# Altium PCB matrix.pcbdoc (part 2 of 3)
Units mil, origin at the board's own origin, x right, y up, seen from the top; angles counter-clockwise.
Board outline 9450 x 9250 mil, 2 copper layers (Top Layer, Bottom Layer); 316 components, 228 nets, 906 pads, 1393 vias.
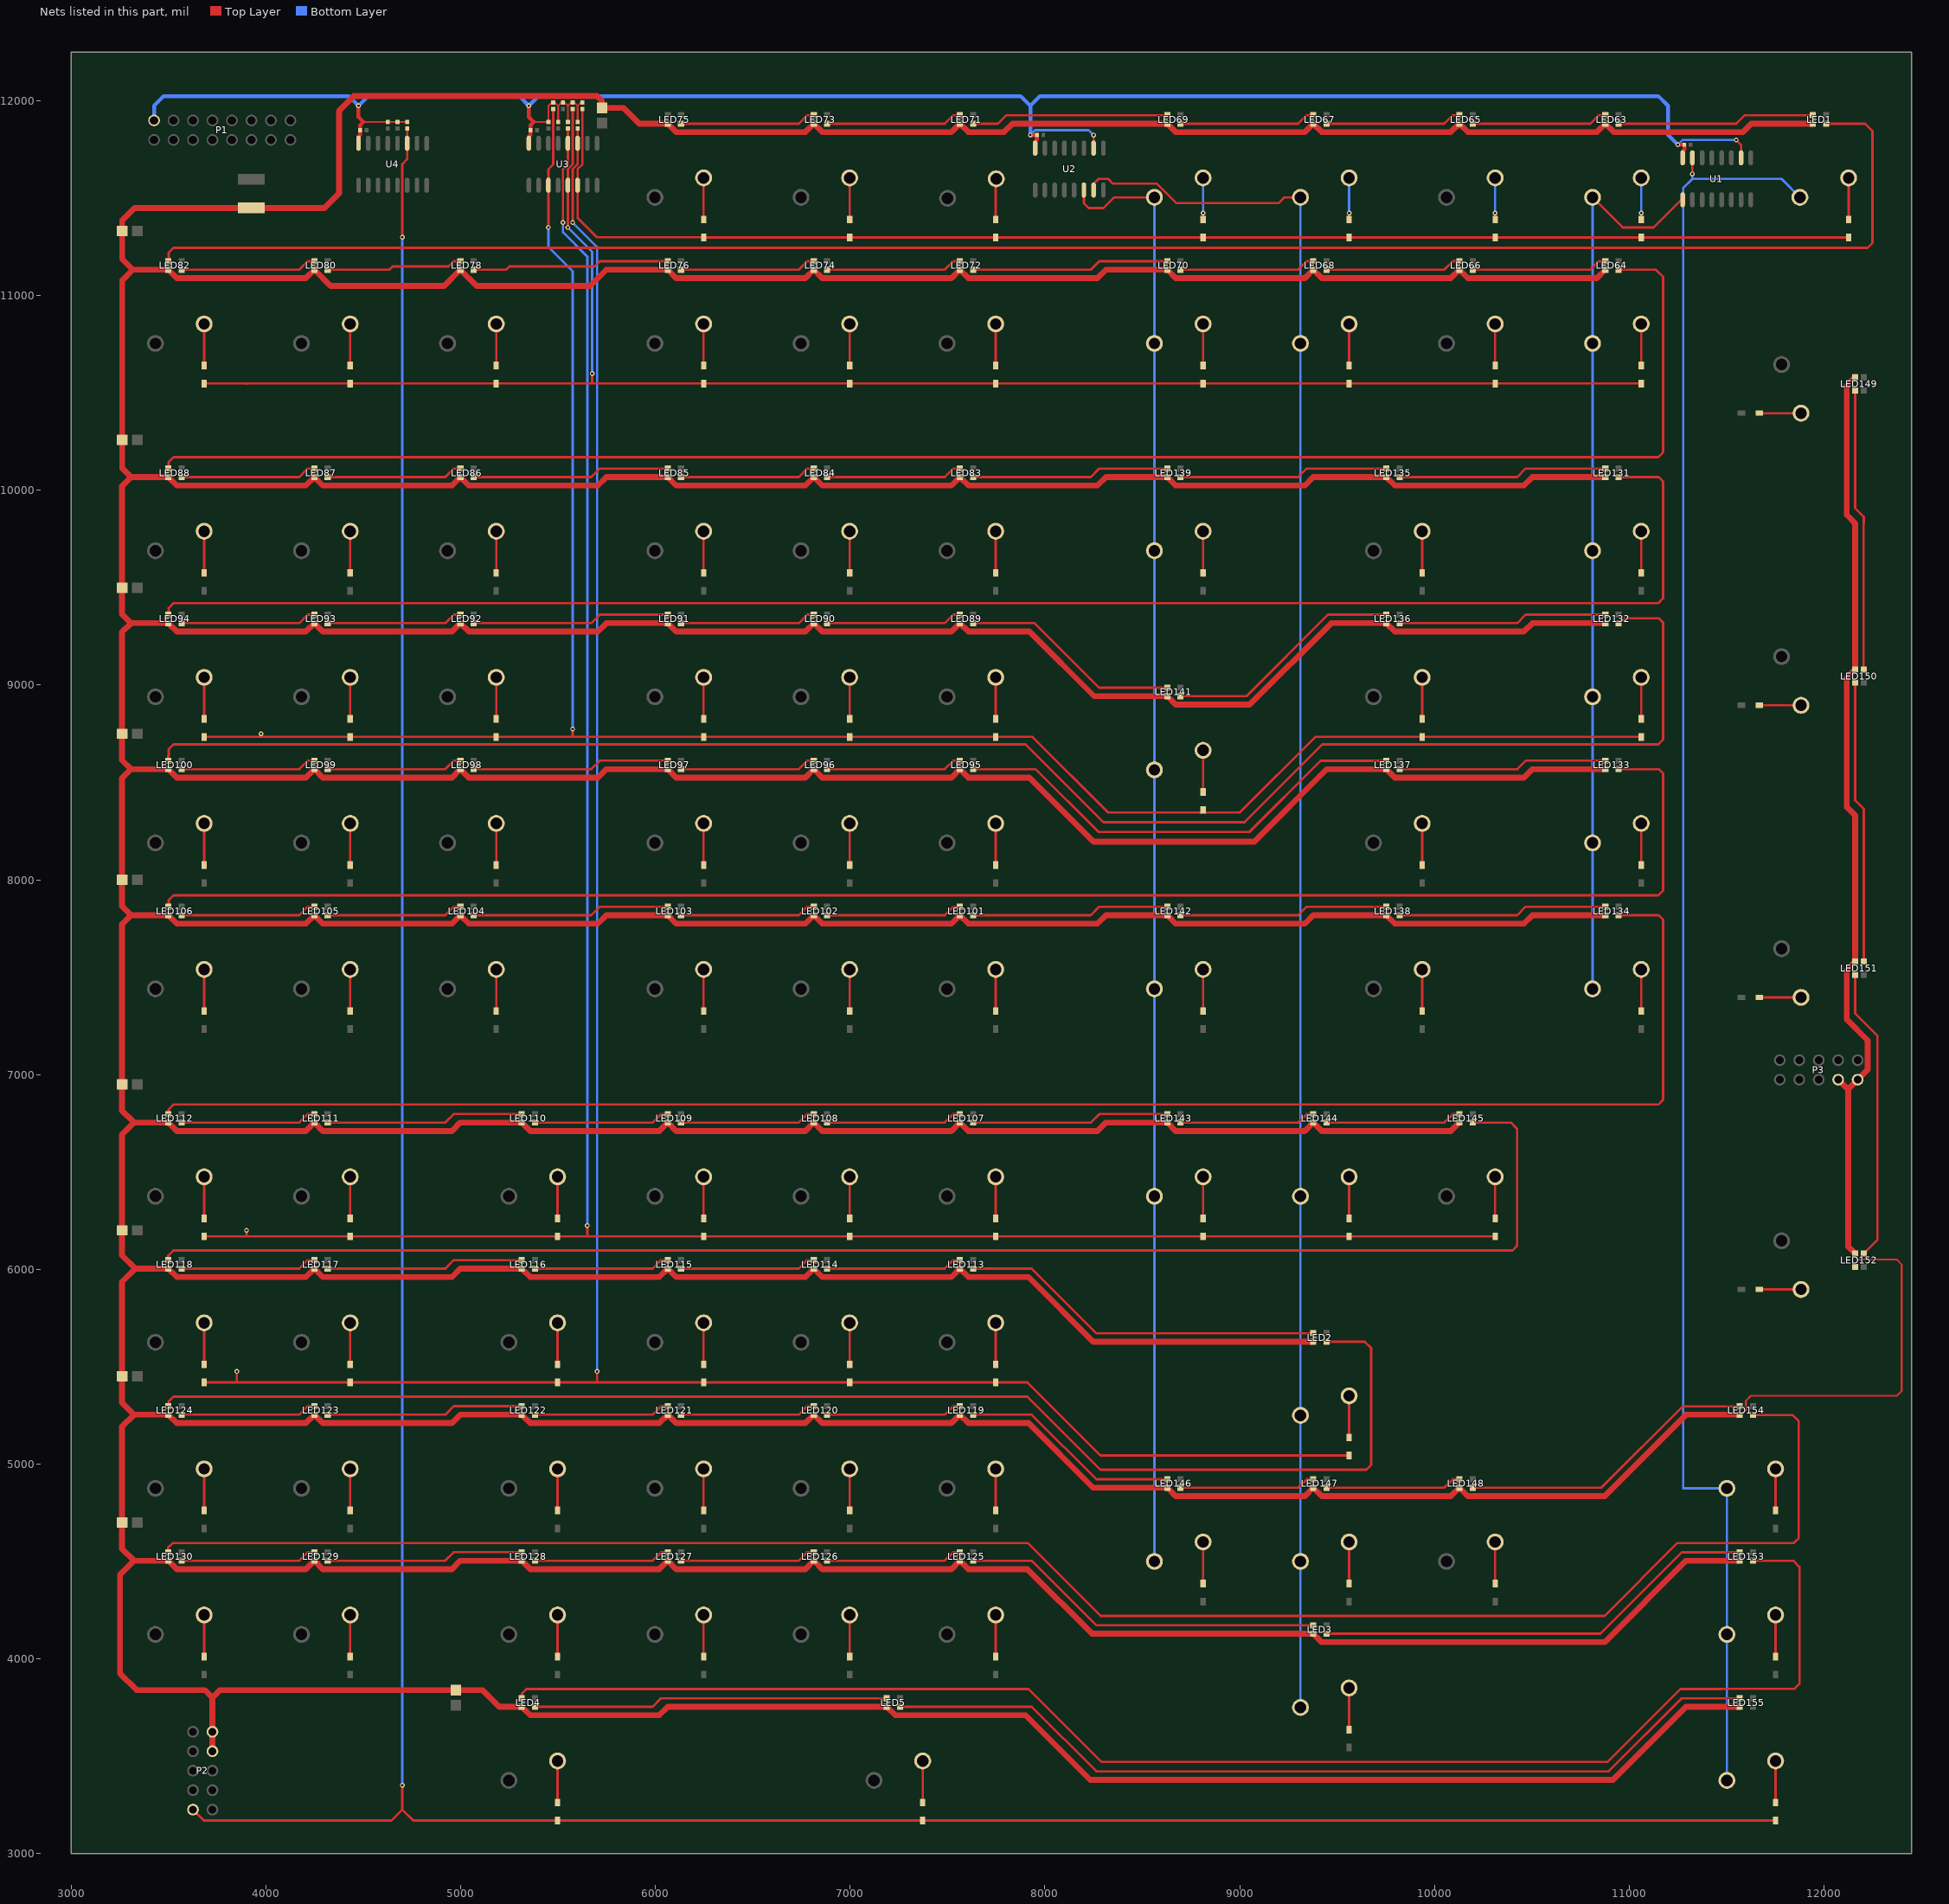
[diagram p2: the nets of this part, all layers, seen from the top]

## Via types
v1: diameter 24.02, hole 12.01, Top Layer to Bottom Layer, 1393 vias

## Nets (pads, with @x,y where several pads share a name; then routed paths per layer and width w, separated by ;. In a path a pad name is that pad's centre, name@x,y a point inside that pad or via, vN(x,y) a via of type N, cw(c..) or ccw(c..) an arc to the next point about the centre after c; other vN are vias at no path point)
3V3: C15.2 C16.2 C17.2 C18.2 P1.1 R1.2 R2.2 R3.2 R4.2 R5.2 R6.2 R7.2 R8.2 R9.2 R10.2 R11.2 U1.10 U1.16 U2.10 U2.16 U3.16 U4.16 | length 10703.2
  Top Layer w10: 4500,11892.04 R9.2@4625,11892.04 R10.2@4675,11892.04 R11.2@4725,11892.04 ; 5375,11892.04 R5.2@5450,11892.04 5450,11975 5467.04,11992.04 R4.2@5475,11992.04 5482.96,11992.04 5500,11975 ; R6.2@5500,11892.04 5500,11975 ; R7.2@5550,11892.04 5550,11975 ; R8.2@5600,11892.04 5600,11975 ; R1.2@5625,11992.04 5617.04,11992.04 5600,11975 ; U2.10@8250,11757.7 v1(8250,11825) ; 5500,11975 5517.04,11992.04 R3.2@5525,11992.04 5532.96,11992.04 5550,11975 ; 5550,11975 5567.04,11992.04 R2.2@5575,11992.04 5582.96,11992.04 5600,11975
  Top Layer w12: v1(11550,11800) 11575,11775 U1.10@11575,11707.7
  Top Layer w20: U4.16@4475,11782.7 4475,11816.54 4483.46,11825 C15.2@4483.46,11850 4483.46,11875.5 4500,11892.04 4475,11917.04 v1(4475,11975) ; U3.16@5350,11782.7 5350,11816.54 5358.46,11825 C17.2@5358.46,11850 5358.46,11875.5 5375,11892.04 5350,11917.04 v1(5350,11975) ; v1(7925,11825) C16.2@7958.46,11825 7958.46,11800 7950,11791.54 U2.16@7950,11757.7 ; v1(11250,11775) C18.2@11283.46,11775 11283.46,11750 11275,11741.54 U1.16@11275,11707.7
  Bottom Layer w10: v1(11250,11775) 11275,11800 v1(11550,11800)
  Bottom Layer w12: v1(7925,11825) 7950,11850 8225,11850 v1(8250,11825)
  Bottom Layer w20: P1.1@3425,11900 3425,11975 3475,12025 4425,12025 v1(4475,11975) 4525,12025 5300,12025 v1(5350,11975) 5400,12025 7875,12025 7925,11975 ; v1(7925,11825) 7925,11975 ; v1(11250,11775) 11200,11825 11200,11975 11150,12025 7975,12025 7925,11975
5V: C1.2 C2.2 C3.1 C4.2 C5.2 C6.2 C7.2 C8.2 C9.2 C10.2 C11.2 F1.2 LED1.4 LED2.4 LED3.4 LED4.4 LED5.4 LED63.4 LED64.4 LED65.4 LED66.4 LED67.4 LED68.4 LED69.4 LED70.4 LED71.4 LED72.4 LED73.4 LED74.4 LED75.4 LED76.4 LED78.4 LED80.4 LED82.4 LED83.4 LED84.4 LED85.4 LED86.4 LED87.4 LED88.4 LED89.4 LED90.4 LED91.4 LED92.4 LED93.4 LED94.4 LED95.4 LED96.4 LED97.4 LED98.4 LED99.4 LED100.4 LED101.4 LED102.4 LED103.4 LED104.4 LED105.4 LED106.4 LED107.4 LED108.4 LED109.4 LED110.4 LED111.4 LED112.4 LED113.4 LED114.4 LED115.4 LED116.4 LED117.4 LED118.4 LED119.4 LED120.4 LED121.4 LED122.4 LED123.4 LED124.4 LED125.4 LED126.4 LED127.4 LED128.4 LED129.4 LED130.4 LED131.4 LED132.4 LED133.4 LED134.4 LED135.4 LED136.4 LED137.4 LED138.4 LED139.4 LED141.4 LED142.4 LED143.4 LED144.4 LED145.4 LED146.4 LED147.4 LED148.4 LED149.4 LED150.4 LED151.4 LED152.4 LED153.4 LED154.4 LED155.4 P2.1 P2.3 P3.1 P3.3 | length 104013.3
  Top Layer w10: LED154.4@11568.24,5253.33 11578.33,5253.33 11600,5275 11600,5325 11625,5350 12375,5350 12400,5375 12400,6025 12375,6050 12175,6050 12161.26,6063.74 LED152.4@12161.26,6080.51
  Top Layer w30: P2.3@3725,3525 P2.1@3725,3625 3725,3800 ; LED129.4@4248.23,4503.33 4204.81,4459.97 3541.59,4459.97 LED130.4@3498.24,4503.33 3321.67,4503.33 ; LED123.4@4248.23,5253.33 4204.81,5209.97 3541.59,5209.97 LED124.4@3498.24,5253.33 3321.67,5253.33 ; LED117.4@4248.23,6003.33 4204.81,5959.97 3541.59,5959.97 LED118.4@3498.24,6003.33 3328.33,6003.33 ; LED111.4@4248.23,6753.33 4204.81,6709.97 3541.59,6709.97 LED112.4@3498.24,6753.33 3321.67,6753.33 ; LED105.4@4248.23,7818.33 4204.81,7774.97 3541.59,7774.97 LED106.4@3498.24,7818.33 3306.67,7818.33 ; LED99.4@4248.23,8568.33 4204.81,8524.97 3541.59,8524.97 LED100.4@3498.24,8568.33 3306.67,8568.33 ; LED93.4@4248.23,9318.33 4204.81,9274.97 3541.59,9274.97 LED94.4@3498.24,9318.33 3306.67,9318.33 ; LED87.4@4248.23,10068.33 4204.81,10024.97 3541.59,10024.97 LED88.4@3498.24,10068.33 3306.67,10068.33 ; LED80.4@4248.23,11133.33 4204.81,11089.97 3541.59,11089.97 LED82.4@3498.24,11133.33 3316.67,11133.33 ; LED129.4@4248.23,4503.33 4291.59,4459.97 4954.79,4459.97 4998.17,4503.33 LED128.4@5313.23,4503.33 5356.59,4459.97 6019.79,4459.97 LED127.4@6063.23,4503.33 ; LED123.4@4248.23,5253.33 4291.59,5209.97 4954.79,5209.97 4998.17,5253.33 ; LED117.4@4248.23,6003.33 4291.59,5959.97 4954.79,5959.97 4998.17,6003.33 ; LED111.4@4248.23,6753.33 4291.59,6709.97 4954.79,6709.97 4998.17,6753.33 LED110.4@5313.23,6753.33 5356.59,6709.97 6019.79,6709.97 LED109.4@6063.23,6753.33 ; LED105.4@4248.23,7818.33 4291.59,7774.97 4954.79,7774.97 LED104.4@4998.23,7818.33 ; LED99.4@4248.23,8568.33 4291.59,8524.97 4954.79,8524.97 LED98.4@4998.23,8568.33 ; LED93.4@4248.23,9318.33 4291.59,9274.97 4954.79,9274.97 LED92.4@4998.23,9318.33 ; LED87.4@4248.23,10068.33 4291.59,10024.97 4954.79,10024.97 LED86.4@4998.23,10068.33 ; LED80.4@4248.23,11133.33 4331.56,11050 4914.84,11050 LED78.4@4998.23,11133.33 ; LED104.4@4998.23,7818.33 5041.59,7774.97 5704.79,7774.97 5748.17,7818.33 LED103.4@6063.23,7818.33 6106.59,7774.97 6769.79,7774.97 LED102.4@6813.23,7818.33 ; LED98.4@4998.23,8568.33 5041.59,8524.97 5704.79,8524.97 5748.17,8568.33 LED97.4@6063.23,8568.33 6106.59,8524.97 6769.79,8524.97 LED96.4@6813.23,8568.33 ; LED92.4@4998.23,9318.33 5041.59,9274.97 5704.79,9274.97 5748.17,9318.33 LED91.4@6063.23,9318.33 6106.59,9274.97 6769.79,9274.97 LED90.4@6813.23,9318.33 ; LED86.4@4998.23,10068.33 5041.59,10024.97 5704.79,10024.97 5748.17,10068.33 LED85.4@6063.23,10068.33 6106.59,10024.97 6769.79,10024.97 LED84.4@6813.23,10068.33 ; LED78.4@4998.23,11133.33 5081.56,11050 5664.84,11050 5748.17,11133.33 LED76.4@6063.23,11133.33 6106.59,11089.97 6769.79,11089.97 LED74.4@6813.23,11133.33 ; 5000,5253.33 LED122.4@5313.23,5253.33 5356.59,5209.97 6019.79,5209.97 LED121.4@6063.23,5253.33 ; 5000,6003.33 LED116.4@5313.23,6003.33 5356.59,5959.97 6019.79,5959.97 LED115.4@6063.23,6003.33 ; LED127.4@6063.23,4503.33 6106.59,4459.97 6769.79,4459.97 LED126.4@6813.23,4503.33 ; LED121.4@6063.23,5253.33 6106.59,5209.97 6769.79,5209.97 LED120.4@6813.23,5253.33 ; LED115.4@6063.23,6003.33 6106.59,5959.97 6769.79,5959.97 LED114.4@6813.23,6003.33 ; LED109.4@6063.23,6753.33 6106.59,6709.97 6769.79,6709.97 LED108.4@6813.23,6753.33 ; LED73.4@6813.23,11883.33 6769.81,11839.97 6106.59,11839.97 LED75.4@6063.23,11883.33 5916.67,11883.33 5835.63,11964.37 C11.2@5725,11964.37 5725,12000 5700,12025 4450,12025 4375,11950 4375,11525 4300,11450 3325,11450 3260.94,11385.94 C1.2@3260.94,11331.5 3260.94,11189.06 3316.67,11133.33 ; LED126.4@6813.23,4503.33 6856.59,4459.97 7519.79,4459.97 LED125.4@7563.23,4503.33 ; LED120.4@6813.23,5253.33 6856.59,5209.97 7519.79,5209.97 LED119.4@7563.23,5253.33 ; LED114.4@6813.23,6003.33 6856.59,5959.97 7519.79,5959.97 LED113.4@7563.23,6003.33 ; LED108.4@6813.23,6753.33 6856.59,6709.97 7519.79,6709.97 LED107.4@7563.23,6753.33 ; LED102.4@6813.23,7818.33 6856.59,7774.97 7519.79,7774.97 LED101.4@7563.23,7818.33 ; LED96.4@6813.23,8568.33 6856.59,8524.97 7519.79,8524.97 LED95.4@7563.23,8568.33 ; LED90.4@6813.23,9318.33 6856.59,9274.97 7519.79,9274.97 LED89.4@7563.23,9318.33 ; LED84.4@6813.23,10068.33 6856.59,10024.97 7519.79,10024.97 LED83.4@7563.23,10068.33 ; LED74.4@6813.23,11133.33 6856.59,11089.97 7519.79,11089.97 LED72.4@7563.23,11133.33 ; LED73.4@6813.23,11883.33 6856.59,11839.97 7519.79,11839.97 LED71.4@7563.23,11883.33 ; LED5.4@7188.23,3753.33 7231.6,3709.97 7900.83,3709.97 8232.48,3378.32 10917.52,3378.32 11292.53,3753.33 LED155.4@11568.24,3753.33 ; LED5.4@7188.23,3753.33 6063.17,3753.33 6019.81,3709.97 5356.59,3709.97 LED4.4@5313.23,3753.33 5196.67,3753.33 5110.63,3839.37 C9.2@4975,3839.37 3764.37,3839.37 3725,3800 ; LED125.4@7563.23,4503.33 7606.59,4459.97 7910,4459.97 8241.64,4128.33 LED3.4@9378.24,4128.33 ; LED119.4@7563.23,5253.33 7606.59,5209.97 7915.83,5209.97 8247.47,4878.33 LED146.4@8628.24,4878.33 8671.59,4834.97 9334.79,4834.97 LED147.4@9378.24,4878.33 ; LED113.4@7563.23,6003.33 7606.59,5959.97 7915.83,5959.97 8247.47,5628.33 LED2.4@9378.24,5628.33 ; LED107.4@7563.23,6753.33 7606.59,6709.97 8269.79,6709.97 8313.17,6753.33 LED143.4@8628.24,6753.33 8671.59,6709.97 9334.79,6709.97 LED144.4@9378.24,6753.33 ; LED101.4@7563.23,7818.33 7606.59,7774.97 8269.79,7774.97 8313.17,7818.33 LED142.4@8628.24,7818.33 ; LED95.4@7563.23,8568.33 7606.59,8524.97 7920.83,8524.97 8250,8195.8 9075,8195.8 9447.53,8568.33 LED137.4@9753.24,8568.33 9796.59,8524.97 10459.79,8524.97 10503.17,8568.33 LED133.4@10878.24,8568.33 ; LED89.4@7563.23,9318.33 7606.59,9274.97 7920.83,9274.97 8252.47,8943.33 LED141.4@8628.24,8943.33 8671.59,8899.97 9051.64,8899.97 9470,9318.33 LED136.4@9753.24,9318.33 9796.59,9274.97 10459.79,9274.97 10503.17,9318.33 LED132.4@10878.24,9318.33 ; LED83.4@7563.23,10068.33 7606.59,10024.97 8269.79,10024.97 8313.17,10068.33 LED139.4@8628.24,10068.33 8671.59,10024.97 9334.79,10024.97 9378.17,10068.33 LED135.4@9753.24,10068.33 9796.59,10024.97 10459.79,10024.97 10503.17,10068.33 LED131.4@10878.24,10068.33 ; LED72.4@7563.23,11133.33 7606.59,11089.97 8269.81,11089.97 8313.17,11133.33 LED70.4@8628.24,11133.33 8671.59,11089.97 9334.79,11089.97 LED68.4@9378.24,11133.33 ; LED71.4@7563.23,11883.33 7606.59,11839.97 7789.97,11839.97 7833.33,11883.33 LED69.4@8628.24,11883.33 8671.59,11839.97 9334.79,11839.97 LED67.4@9378.24,11883.33 ; LED142.4@8628.24,7818.33 8671.6,7774.97 9334.8,7774.97 9378.17,7818.32 LED138.4@9753.24,7818.33 9796.59,7774.97 10459.79,7774.97 10503.17,7818.33 LED134.4@10878.24,7818.33 ; LED3.4@9378.24,4128.33 9421.6,4084.97 10874.17,4084.97 11292.53,4503.33 LED153.4@11568.24,4503.33 ; LED147.4@9378.24,4878.33 9421.59,4834.97 10084.79,4834.97 LED148.4@10128.24,4878.33 ; LED144.4@9378.24,6753.33 9421.59,6709.97 10084.79,6709.97 LED145.4@10128.24,6753.33 ; LED68.4@9378.24,11133.33 9421.59,11089.97 10084.79,11089.97 LED66.4@10128.24,11133.33 ; LED67.4@9378.24,11883.33 9421.59,11839.97 10084.79,11839.97 LED65.4@10128.24,11883.33 ; LED148.4@10128.24,4878.33 10171.59,4834.97 10874.17,4834.97 11292.53,5253.33 LED154.4@11568.24,5253.33 ; LED66.4@10128.24,11133.33 10171.59,11089.97 10834.79,11089.97 LED64.4@10878.24,11133.33 ; LED65.4@10128.24,11883.33 10171.59,11839.97 10834.79,11839.97 LED63.4@10878.24,11883.33 ; LED63.4@10878.24,11883.33 10921.59,11839.97 11584.79,11839.97 11628.17,11883.33 LED1.4@11943.24,11883.33 ; P3.3@12073.73,6973.74 12125,6922.48 12125,6125 ; 12125,6116.77 LED152.4@12161.26,6080.51 ; 12125,6925.01 P3.1@12173.73,6973.74 12225,7025 12225,7175 12117.91,7282.1 12117.91,7537.15 LED151.4@12161.26,7580.51 12161.26,8330.57 12117.91,8373.93 12117.91,9037.15 LED150.4@12161.26,9080.51 12161.26,9830.57 12117.91,9873.93 12117.91,10537.15 LED149.4@12161.26,10580.51 ; 3306.67,7818.33 3260.63,7864.37 C10.2@3260.63,8000 3260.63,8522.29 3306.67,8568.33 ; 3306.67,7818.33 3260.63,7772.29 C4.2@3260.63,6950 3260.63,6814.37 3321.67,6753.33 ; 3306.67,8568.33 3260.63,8614.37 C6.2@3260.63,8750 3260.63,9272.29 3306.67,9318.33 ; 3306.67,9318.33 3260.63,9364.37 C3.1@3260.63,9500 3260.63,10022.29 3306.67,10068.33 ; 3306.67,10068.33 3260.94,10114.06 C2.2@3260.94,10259.66 3260.94,11077.59 3316.67,11133.33 ; 3321.67,4503.33 3260.63,4564.37 C8.2@3260.63,4700 3260.63,5192.29 3321.67,5253.33 ; 3321.67,4503.33 3250,4431.66 3250,3925 3335.63,3839.37 3685.63,3839.37 3725,3800 ; 3321.67,5253.33 3260.63,5314.37 C7.2@3260.63,5450 3260.63,5935.63 3328.33,6003.33 ; 3321.67,6753.33 3260.63,6692.29 C5.2@3260.63,6200 3260.63,6071.03 3328.33,6003.33
$1I2620\$1N2306: D1.1 SW1.1 | length 213.8
  Top Layer w12: D1.1@12127.29,11391.13 SW1.1@12127.29,11604.97
$1I2664\$1N2306: D63.1 SW63.1 | length 213.8
  Top Layer w12: D63.1@11062.29,11391.13 v1(11062.29,11425)
  Bottom Layer w12: v1(11062.29,11425) SW63.1@11062.29,11604.97
$1I2686\$1N2306: D64.1 SW64.1 | length 213.8
  Top Layer w12: D64.1@11062.29,10641.13 SW64.1@11062.29,10854.97
$1I2730\$1N2306: D65.1 SW65.1 | length 213.8
  Top Layer w12: D65.1@10312.29,11391.13 v1(10312.29,11425)
  Bottom Layer w12: v1(10312.29,11425) SW65.1@10312.29,11604.97
$1I2752\$1N2306: D66.1 SW66.1 | length 213.8
  Top Layer w12: D66.1@10312.29,10641.13 SW66.1@10312.29,10854.97
$1I2774\$1N2306: D67.1 SW67.1 | length 213.8
  Top Layer w12: D67.1@9562.29,11391.13 v1(9562.29,11425)
  Bottom Layer w12: v1(9562.29,11425) SW67.1@9562.29,11604.97
$1I2796\$1N2306: D68.1 SW68.1 | length 213.8
  Top Layer w12: D68.1@9562.29,10641.13 SW68.1@9562.29,10854.97
$1I2818\$1N2306: D69.1 SW69.1 | length 213.8
  Top Layer w12: D69.1@8812.29,11391.13 v1(8812.29,11425)
  Bottom Layer w12: v1(8812.29,11425) SW69.1@8812.29,11604.97
$1I2840\$1N2306: D70.1 SW70.1 | length 213.8
  Top Layer w12: D70.1@8812.29,10641.13 SW70.1@8812.29,10854.97
$1I4022\$1N2306: D71.1 SW71.1 | length 213.8
  Top Layer w12: D71.1@7747.29,11391.13 SW71.1@7747.29,11604.97
$1I4044\$1N2306: D72.1 SW72.1 | length 213.8
  Top Layer w12: D72.1@7747.29,10641.13 SW72.1@7747.29,10854.97
$1I4066\$1N2306: D73.1 SW73.1 | length 213.8
  Top Layer w12: D73.1@6997.29,11391.13 SW73.1@6997.29,11604.97
$1I4088\$1N2306: D74.1 SW74.1 | length 213.8
  Top Layer w12: D74.1@6997.29,10641.13 SW74.1@6997.29,10854.97
$1I4110\$1N2306: D75.1 SW75.1 | length 213.8
  Top Layer w12: D75.1@6247.29,11391.13 SW75.1@6247.29,11604.97
$1I4132\$1N2306: D76.1 SW76.1 | length 213.8
  Top Layer w12: D76.1@6247.29,10641.13 SW76.1@6247.29,10854.97
$1I4184\$1N2306: D78.1 SW78.1 | length 213.8
  Top Layer w12: D78.1@5182.29,10641.13 SW78.1@5182.29,10854.97
$1I4228\$1N2306: D80.1 SW80.1 | length 213.8
  Top Layer w12: D80.1@4432.29,10641.13 SW80.1@4432.29,10854.97
$1I4272\$1N2306: D82.1 SW82.1 | length 213.8
  Top Layer w12: D82.1@3682.29,10641.13 SW82.1@3682.29,10854.97
$1I4438\$1N2306: D83.1 SW83.1 | length 213.8
  Top Layer w12: D83.1@7747.29,9576.13 SW83.1@7747.29,9789.97
$1I4460\$1N2306: D84.1 SW84.1 | length 213.8
  Top Layer w12: D84.1@6997.29,9576.13 SW84.1@6997.29,9789.97
$1I4482\$1N2306: D85.1 SW85.1 | length 213.8
  Top Layer w12: D85.1@6247.29,9576.13 SW85.1@6247.29,9789.97
$1I4504\$1N2306: D86.1 SW86.1 | length 213.8
  Top Layer w12: D86.1@5182.29,9576.13 SW86.1@5182.29,9789.97
$1I4526\$1N2306: D87.1 SW87.1 | length 213.8
  Top Layer w12: D87.1@4432.29,9576.13 SW87.1@4432.29,9789.97
$1I4548\$1N2306: D88.1 SW88.1 | length 213.8
  Top Layer w12: D88.1@3682.29,9576.13 SW88.1@3682.29,9789.97
$1I4578\$1N2306: D89.1 SW89.1 | length 213.8
  Top Layer w12: D89.1@7747.29,8826.13 SW89.1@7747.29,9039.97
$1I4600\$1N2306: D90.1 SW90.1 | length 213.8
  Top Layer w12: D90.1@6997.29,8826.13 SW90.1@6997.29,9039.97
$1I4622\$1N2306: D91.1 SW91.1 | length 213.8
  Top Layer w12: D91.1@6247.29,8826.13 SW91.1@6247.29,9039.97
$1I4644\$1N2306: D92.1 SW92.1 | length 213.8
  Top Layer w12: D92.1@5182.29,8826.13 SW92.1@5182.29,9039.97
$1I4666\$1N2306: D93.1 SW93.1 | length 213.8
  Top Layer w12: D93.1@4432.29,8826.13 SW93.1@4432.29,9039.97
$1I4688\$1N2306: D94.1 SW94.1 | length 213.8
  Top Layer w12: D94.1@3682.29,8826.13 SW94.1@3682.29,9039.97
$1I4718\$1N2306: D95.1 SW95.1 | length 213.8
  Top Layer w12: D95.1@7747.29,8076.13 SW95.1@7747.29,8289.97
$1I4740\$1N2306: D96.1 SW96.1 | length 213.8
  Top Layer w12: D96.1@6997.29,8076.13 SW96.1@6997.29,8289.97
$1I4762\$1N2306: D97.1 SW97.1 | length 213.8
  Top Layer w12: D97.1@6247.29,8076.13 SW97.1@6247.29,8289.97
$1I4784\$1N2306: D98.1 SW98.1 | length 213.8
  Top Layer w12: D98.1@5182.29,8076.13 SW98.1@5182.29,8289.97
$1I4806\$1N2306: D99.1 SW99.1 | length 213.8
  Top Layer w12: D99.1@4432.29,8076.13 SW99.1@4432.29,8289.97
$1I4828\$1N2306: D100.1 SW100.1 | length 213.8
  Top Layer w12: D100.1@3682.29,8076.13 SW100.1@3682.29,8289.97
$1I4858\$1N2306: D101.1 SW101.1 | length 213.8
  Top Layer w12: D101.1@7747.29,7326.13 SW101.1@7747.29,7539.97
$1I4880\$1N2306: D102.1 SW102.1 | length 213.8
  Top Layer w12: D102.1@6997.29,7326.13 SW102.1@6997.29,7539.97
$1I4902\$1N2306: D103.1 SW103.1 | length 213.8
  Top Layer w12: D103.1@6247.29,7326.13 SW103.1@6247.29,7539.97
$1I4924\$1N2306: D104.1 SW104.1 | length 213.8
  Top Layer w12: D104.1@5182.29,7326.13 SW104.1@5182.29,7539.97
$1I4946\$1N2306: D105.1 SW105.1 | length 213.8
  Top Layer w12: D105.1@4432.29,7326.13 SW105.1@4432.29,7539.97
$1I4968\$1N2306: D106.1 SW106.1 | length 213.8
  Top Layer w12: D106.1@3682.29,7326.13 SW106.1@3682.29,7539.97
$1I4998\$1N2306: D107.1 SW107.1 | length 213.8
  Top Layer w12: D107.1@7747.29,6261.13 SW107.1@7747.29,6474.97
$1I5020\$1N2306: D108.1 SW108.1 | length 213.8
  Top Layer w12: D108.1@6997.29,6261.13 SW108.1@6997.29,6474.97
$1I5042\$1N2306: D109.1 SW109.1 | length 213.8
  Top Layer w12: D109.1@6247.29,6261.13 SW109.1@6247.29,6474.97
$1I5064\$1N2306: D110.1 SW110.1 | length 213.8
  Top Layer w12: D110.1@5497.29,6261.13 SW110.1@5497.29,6474.97
$1I5086\$1N2306: D111.1 SW111.1 | length 213.8
  Top Layer w12: D111.1@4432.29,6261.13 SW111.1@4432.29,6474.97
$1I5108\$1N2306: D112.1 SW112.1 | length 213.8
  Top Layer w12: D112.1@3682.29,6261.13 SW112.1@3682.29,6474.97
$1I5424\$1N2306: D113.1 SW113.1 | length 213.8
  Top Layer w12: D113.1@7747.29,5511.13 SW113.1@7747.29,5724.97
$1I5446\$1N2306: D114.1 SW114.1 | length 213.8
  Top Layer w12: D114.1@6997.29,5511.13 SW114.1@6997.29,5724.97
$1I5468\$1N2306: D115.1 SW115.1 | length 213.8
  Top Layer w12: D115.1@6247.29,5511.13 SW115.1@6247.29,5724.97
$1I5490\$1N2306: D116.1 SW116.1 | length 213.8
  Top Layer w12: D116.1@5497.29,5511.13 SW116.1@5497.29,5724.97
$1I5512\$1N2306: D117.1 SW117.1 | length 213.8
  Top Layer w12: D117.1@4432.29,5511.13 SW117.1@4432.29,5724.97
$1I5534\$1N2306: D118.1 SW118.1 | length 213.8
  Top Layer w12: D118.1@3682.29,5511.13 SW118.1@3682.29,5724.97
$1I5566\$1N2306: D119.1 SW119.1 | length 213.8
  Top Layer w12: D119.1@7747.29,4761.13 SW119.1@7747.29,4974.97
$1I5588\$1N2306: D120.1 SW120.1 | length 213.8
  Top Layer w12: D120.1@6997.29,4761.13 SW120.1@6997.29,4974.97
$1I5610\$1N2306: D121.1 SW121.1 | length 213.8
  Top Layer w12: D121.1@6247.29,4761.13 SW121.1@6247.29,4974.97
$1I5632\$1N2306: D122.1 SW122.1 | length 213.8
  Top Layer w12: D122.1@5497.29,4761.13 SW122.1@5497.29,4974.97
$1I5654\$1N2306: D123.1 SW123.1 | length 213.8
  Top Layer w12: D123.1@4432.29,4761.13 SW123.1@4432.29,4974.97
$1I5676\$1N2306: D124.1 SW124.1 | length 213.8
  Top Layer w12: D124.1@3682.29,4761.13 SW124.1@3682.29,4974.97
$1I5708\$1N2306: D125.1 SW125.1 | length 213.8
  Top Layer w12: D125.1@7747.29,4011.13 SW125.1@7747.29,4224.97
$1I5730\$1N2306: D126.1 SW126.1 | length 213.8
  Top Layer w12: D126.1@6997.29,4011.13 SW126.1@6997.29,4224.97
$1I5752\$1N2306: D127.1 SW127.1 | length 213.8
  Top Layer w12: D127.1@6247.29,4011.13 SW127.1@6247.29,4224.97
$1I5774\$1N2306: D128.1 SW128.1 | length 213.8
  Top Layer w12: D128.1@5497.29,4011.13 SW128.1@5497.29,4224.97
$1I5796\$1N2306: D129.1 SW129.1 | length 213.8
  Top Layer w12: D129.1@4432.29,4011.13 SW129.1@4432.29,4224.97
$1I5818\$1N2306: D130.1 SW130.1 | length 213.8
  Top Layer w12: D130.1@3682.29,4011.13 SW130.1@3682.29,4224.97
$1I6023\$1N2306: D131.1 SW131.1 | length 213.8
  Top Layer w12: D131.1@11062.29,9576.13 SW131.1@11062.29,9789.97
$1I6045\$1N2306: D132.1 SW132.1 | length 213.8
  Top Layer w12: D132.1@11062.29,8826.13 SW132.1@11062.29,9039.97
$1I6067\$1N2306: D133.1 SW133.1 | length 213.8
  Top Layer w12: D133.1@11062.29,8076.13 SW133.1@11062.29,8289.97
$1I6089\$1N2306: D134.1 SW134.1 | length 213.8
  Top Layer w12: D134.1@11062.29,7326.13 SW134.1@11062.29,7539.97
$1I6155\$1N2306: D136.1 SW136.1 | length 213.8
  Top Layer w12: D136.1@9937.29,8826.13 SW136.1@9937.29,9039.97
$1I6177\$1N2306: D135.1 SW135.1 | length 213.8
  Top Layer w12: D135.1@9937.29,9576.13 SW135.1@9937.29,9789.97
$1I6199\$1N2306: D138.1 SW138.1 | length 213.8
  Top Layer w12: D138.1@9937.29,7326.13 SW138.1@9937.29,7539.97
$1I6221\$1N2306: D137.1 SW137.1 | length 213.8
  Top Layer w12: D137.1@9937.29,8076.13 SW137.1@9937.29,8289.97
$1I6243\$1N2306: D139.1 SW139.1 | length 213.8
  Top Layer w12: D139.1@8812.29,9576.13 SW139.1@8812.29,9789.97
$1I6287\$1N2306: D141.1 SW141.1 | length 213.8
  Top Layer w12: D141.1@8812.29,8451.13 SW141.1@8812.29,8664.97
$1I6309\$1N2306: D142.1 SW142.1 | length 213.8
  Top Layer w12: D142.1@8812.29,7326.13 SW142.1@8812.29,7539.97
$1I6507\$1N2306: D143.1 SW143.1 | length 213.8
  Top Layer w12: D143.1@8812.29,6261.13 SW143.1@8812.29,6474.97
$1I6529\$1N2306: D144.1 SW144.1 | length 213.8
  Top Layer w12: D144.1@9562.29,6261.13 SW144.1@9562.29,6474.97
$1I6553\$1N2306: D145.1 SW145.1 | length 213.8
  Top Layer w12: D145.1@10312.29,6261.13 SW145.1@10312.29,6474.97
$1I6621\$1N2306: D146.1 SW146.1 | length 213.8
  Top Layer w12: D146.1@8812.29,4386.13 SW146.1@8812.29,4599.97
$1I6643\$1N2306: D147.1 SW147.1 | length 213.8
  Top Layer w12: D147.1@9562.29,4386.13 SW147.1@9562.29,4599.97
$1I6665\$1N2306: D148.1 SW148.1 | length 213.8
  Top Layer w12: D148.1@10312.29,4386.13 SW148.1@10312.29,4599.97
$1I6691\$1N2306: D2.1 SW2.1 | length 213.8
  Top Layer w12: D2.1@9562.29,5136.13 SW2.1@9562.29,5349.97
$1I6735\$1N2306: D3.1 SW3.1 | length 213.8
  Top Layer w12: D3.1@9562.29,3636.13 SW3.1@9562.29,3849.97
$1I6783\$1N2306: D4.1 SW4.1 | length 213.8
  Top Layer w12: D4.1@5497.29,3261.13 SW4.1@5497.29,3474.97
$1I6805\$1N2306: D149.1 SW149.1 | length 213.8
  Top Layer w12: D149.1@11669.07,10396.45 SW149.1@11882.91,10396.45
$1I6827\$1N2306: D150.1 SW150.1 | length 213.8
  Top Layer w12: D150.1@11669.07,8896.45 SW150.1@11882.91,8896.45
$1I6849\$1N2306: D151.1 SW151.1 | length 213.8
  Top Layer w12: D151.1@11669.07,7396.45 SW151.1@11882.91,7396.45
$1I6871\$1N2306: D152.1 SW152.1 | length 213.8
  Top Layer w12: D152.1@11669.07,5896.45 SW152.1@11882.91,5896.45
$1I6871\DO: LED152.1
$1I6893\$1N2306: D5.1 SW5.1 | length 213.8
  Top Layer w12: D5.1@7372.29,3261.13 SW5.1@7372.29,3474.97
$1I6915\$1N2306: D153.1 SW153.1 | length 213.8
  Top Layer w12: D153.1@11752.29,4011.13 SW153.1@11752.29,4224.97
$1I6959\$1N2306: D154.1 SW154.1 | length 213.8
  Top Layer w12: D154.1@11752.29,4761.13 SW154.1@11752.29,4974.97
$1I6981\$1N2306: D155.1 SW155.1 | length 213.8
  Top Layer w12: D155.1@11752.29,3261.13 SW155.1@11752.29,3474.97
$1N3652: LED67.3 LED69.1 | length 694.9
  Top Layer w12: LED69.1@8701.35,11883.33 9300.59,11883.33 9344.15,11926.94 LED67.3@9378.19,11926.94
$1N3654: LED65.3 LED67.1 | length 694.9
  Top Layer w12: LED67.1@9451.35,11883.33 10050.59,11883.33 10094.15,11926.94 LED65.3@10128.19,11926.94
$1N3656: LED63.3 LED65.1 | length 694.9
  Top Layer w12: LED65.1@10201.35,11883.33 10800.59,11883.33 10844.15,11926.94 LED63.3@10878.19,11926.94
$1N3658: LED1.3 LED63.1 | length 1010.1
  Top Layer w12: LED63.1@10951.35,11883.33 11550.59,11883.33 11594.15,11926.94 11942.93,11926.94 LED1.3@11943.24,11926.64
$1N3660: LED64.3 LED66.1 | length 694.9
  Top Layer w12: LED66.1@10201.35,11133.33 10800.59,11133.33 10844.15,11176.94 LED64.3@10878.19,11176.94
$1N3662: LED66.3 LED68.1 | length 694.9
  Top Layer w12: LED68.1@9451.35,11133.33 10050.59,11133.33 10094.15,11176.94 LED66.3@10128.19,11176.94
$1N3664: LED68.3 LED70.1 | length 694.9
  Top Layer w12: LED70.1@8701.35,11133.33 9300.59,11133.33 9344.15,11176.94 LED68.3@9378.19,11176.94
$1N3668: D1.2 D63.2 D65.2 D67.2 D69.2 D71.2 D73.2 D75.2 R1.1 U3.6 | length 7137.5
  Top Layer w12: R1.1@5625,11957.96 5625,11675 5600,11650 U3.6@5600,11567.3 5600,11400 5700,11300 6246.1,11300 D75.2@6247.29,11298.81 D73.2@6997.29,11298.81 D71.2@7747.29,11298.81 D69.2@8812.29,11298.81 D67.2@9562.29,11298.81 D65.2@10312.29,11298.81 D63.2@11062.29,11298.81 D1.2@12127.29,11298.81
$1N3676: D64.2 D66.2 D68.2 D70.2 D72.2 D74.2 D76.2 D78.2 D80.2 D82.2 R2.1 U3.5 | length 8853.1
  Top Layer w12: D82.2@3682.29,10548.81 3901.27,10548.81 ; 3900,10547.54 3901.27,10548.81 ; v1(5550,11350) U3.5@5550,11567.3 5550,11650 5575,11675 R2.1@5575,11957.96 ; v1(5675,10600) 5675,10548.89 5674.92,10548.81 ; D64.2@11062.29,10548.81 D66.2@10312.29,10548.81 D68.2@9562.29,10548.81 D70.2@8812.29,10548.81 D72.2@7747.29,10548.81 D74.2@6997.29,10548.81 D76.2@6247.29,10548.81 5674.92,10548.81 ; 3901.27,10548.81 D80.2@4432.29,10548.81 D78.2@5182.29,10548.81 5674.92,10548.81
  Bottom Layer w12: v1(5550,11350) 5675,11225 v1(5675,10600)
$1N3683: SW69.2 SW70.2 SW139.2 SW141.2 SW142.2 SW143.2 SW146.2 U2.6 | length 7467.7
  Top Layer w12: U2.6@8200,11542.3 8200,11475 8225,11450 8300,11450 8354.97,11504.97 SW69.2@8562.29,11504.97
  Bottom Layer w12: SW146.2@8562.29,4499.97 SW143.2@8562.29,6374.97 SW142.2@8562.29,7439.97 SW141.2@8562.29,8564.97 SW139.2@8562.29,9689.97 SW70.2@8562.29,10754.97 SW69.2@8562.29,11504.97
$1N3688: SW2.2 SW3.2 SW67.2 SW68.2 SW144.2 SW147.2 U2.7 | length 8924.5
  Top Layer w12: U2.7@8250,11542.3 8250,11575 8275,11600 8325,11600 8350,11575 8575,11575 8675,11475 9200,11475 9229.97,11504.97 SW67.2@9312.29,11504.97
  Bottom Layer w12: SW3.2@9312.29,3749.97 SW147.2@9312.29,4499.97 SW2.2@9312.29,5249.97 SW144.2@9312.29,6374.97 SW68.2@9312.29,10754.97 SW67.2@9312.29,11504.97
$1N3698: SW63.2 SW64.2 SW131.2 SW132.2 SW133.2 SW134.2 U1.1 | length 4650.8
  Top Layer w12: SW63.2@10812.29,11504.97 10967.26,11350 11125,11350 11267.3,11492.3 U1.1@11275,11492.3
  Bottom Layer w12: SW134.2@10812.29,7439.97 SW133.2@10812.29,8189.97 SW132.2@10812.29,8939.97 SW131.2@10812.29,9689.97 SW64.2@10812.29,10754.97 SW63.2@10812.29,11504.97
$1N4154: LED71.3 LED73.1 | length 694.9
  Top Layer w12: LED73.1@6886.35,11883.33 7485.59,11883.33 7529.15,11926.94 LED71.3@7563.19,11926.94
$1N4156: LED72.3 LED74.1 | length 694.9
  Top Layer w12: LED74.1@6886.35,11133.33 7485.59,11133.33 7529.15,11176.94 LED72.3@7563.19,11176.94
$1N4158: LED73.3 LED75.1 | length 694.9
  Top Layer w12: LED75.1@6136.35,11883.33 6735.59,11883.33 6779.15,11926.94 LED73.3@6813.19,11926.94
$1N4160: LED74.3 LED76.1 | length 694.9
  Top Layer w12: LED76.1@6136.35,11133.33 6735.59,11133.33 6779.15,11176.94 LED74.3@6813.19,11176.94
$1N4296: LED78.3 LED80.1 | length 699.9
  Top Layer w12: LED80.1@4316.35,11133.33 4633.33,11133.33 4650,11150 4937.23,11150 4964.15,11176.94 LED78.3@4998.19,11176.94
$1N4300: LED80.3 LED82.1 | length 694.9
  Top Layer w12: LED82.1@3571.35,11133.33 4170.59,11133.33 4214.15,11176.94 LED80.3@4248.19,11176.94
$1N4304: LED69.3 LED71.1 | length 1010.1
  Top Layer w12: LED71.1@7636.35,11883.33 7758.35,11883.33 7801.91,11926.94 8627.93,11926.94 LED69.3@8628.24,11926.64
$1N4570: LED83.3 LED84.1 | length 694.9
  Top Layer w12: LED84.1@6886.35,10068.33 7485.59,10068.33 7529.15,10111.94 LED83.3@7563.19,10111.94
$1N4572: LED84.3 LED85.1 | length 694.9
  Top Layer w12: LED85.1@6136.35,10068.33 6735.59,10068.33 6779.15,10111.94 LED84.3@6813.19,10111.94
$1N4574: LED86.3 LED87.1 | length 694.9
  Top Layer w12: LED87.1@4321.35,10068.33 4920.59,10068.33 4964.15,10111.94 LED86.3@4998.19,10111.94
$1N4576: LED87.3 LED88.1 | length 694.9
  Top Layer w12: LED88.1@3571.35,10068.33 4170.59,10068.33 4214.15,10111.94 LED87.3@4248.19,10111.94
$1N4710: LED89.3 LED90.1 | length 694.9
  Top Layer w12: LED90.1@6886.35,9318.33 7485.59,9318.33 7529.15,9361.94 LED89.3@7563.19,9361.94
$1N4712: LED90.3 LED91.1 | length 694.9
  Top Layer w12: LED91.1@6136.35,9318.33 6735.59,9318.33 6779.15,9361.94 LED90.3@6813.19,9361.94
$1N4714: LED92.3 LED93.1 | length 694.9
  Top Layer w12: LED93.1@4321.35,9318.33 4920.59,9318.33 4964.15,9361.94 LED92.3@4998.19,9361.94
$1N4716: LED93.3 LED94.1 | length 694.9
  Top Layer w12: LED94.1@3571.35,9318.33 4170.59,9318.33 4214.15,9361.94 LED93.3@4248.19,9361.94
$1N4850: LED95.3 LED96.1 | length 694.9
  Top Layer w12: LED96.1@6886.35,8568.33 7485.59,8568.33 7529.15,8611.94 LED95.3@7563.19,8611.94
$1N4852: LED96.3 LED97.1 | length 694.9
  Top Layer w12: LED97.1@6136.35,8568.33 6735.59,8568.33 6779.15,8611.94 LED96.3@6813.19,8611.94
$1N4854: LED98.3 LED99.1 | length 694.9
  Top Layer w12: LED99.1@4321.35,8568.33 4920.59,8568.33 4964.15,8611.94 LED98.3@4998.19,8611.94
$1N4856: LED99.3 LED100.1 | length 694.9
  Top Layer w12: LED100.1@3571.35,8568.33 4170.59,8568.33 4214.15,8611.94 LED99.3@4248.19,8611.94
$1N4990: LED101.3 LED102.1 | length 694.9
  Top Layer w12: LED102.1@6886.35,7818.33 7485.59,7818.33 7529.15,7861.94 LED101.3@7563.19,7861.94
$1N4992: LED102.3 LED103.1 | length 694.9
  Top Layer w12: LED103.1@6136.35,7818.33 6735.59,7818.33 6779.15,7861.94 LED102.3@6813.19,7861.94
$1N4994: LED104.3 LED105.1 | length 694.9
  Top Layer w12: LED105.1@4321.35,7818.33 4920.59,7818.33 4964.15,7861.94 LED104.3@4998.19,7861.94
$1N4996: LED105.3 LED106.1 | length 694.9
  Top Layer w12: LED106.1@3571.35,7818.33 4170.59,7818.33 4214.15,7861.94 LED105.3@4248.19,7861.94
$1N5130: LED107.3 LED108.1 | length 694.9
  Top Layer w12: LED108.1@6886.35,6753.33 7485.59,6753.33 7529.15,6796.94 LED107.3@7563.19,6796.94
$1N5132: LED108.3 LED109.1 | length 694.9
  Top Layer w12: LED109.1@6136.35,6753.33 6735.59,6753.33 6779.15,6796.94 LED108.3@6813.19,6796.94
$1N5134: LED110.3 LED111.1 | length 1010.1
  Top Layer w12: LED111.1@4321.35,6753.33 4920.59,6753.33 4964.15,6796.94 5312.93,6796.94 LED110.3@5313.24,6796.64
$1N5136: LED111.3 LED112.1 | length 694.9
  Top Layer w12: LED112.1@3571.35,6753.33 4170.59,6753.33 4214.15,6796.94 LED111.3@4248.19,6796.94
$1N5138: LED109.3 LED110.1 | length 694.9
  Top Layer w12: LED110.1@5386.35,6753.33 5985.59,6753.33 6029.15,6796.94 LED109.3@6063.19,6796.94
$1N5556: LED113.3 LED114.1 | length 694.9
  Top Layer w12: LED114.1@6886.35,6003.33 7485.59,6003.33 7529.15,6046.94 LED113.3@7563.19,6046.94
$1N5558: LED114.3 LED115.1 | length 694.9
  Top Layer w12: LED115.1@6136.35,6003.33 6735.59,6003.33 6779.15,6046.94 LED114.3@6813.19,6046.94
$1N5560: LED116.3 LED117.1 | length 1010.1
  Top Layer w12: LED117.1@4321.35,6003.33 4920.59,6003.33 4964.15,6046.94 5312.93,6046.94 LED116.3@5313.24,6046.64
$1N5562: LED117.3 LED118.1 | length 694.9
  Top Layer w12: LED118.1@3571.35,6003.33 4170.59,6003.33 4214.15,6046.94 LED117.3@4248.19,6046.94
$1N5564: LED115.3 LED116.1 | length 694.9
  Top Layer w12: LED116.1@5386.35,6003.33 5985.59,6003.33 6029.15,6046.94 LED115.3@6063.19,6046.94
$1N5698: LED119.3 LED120.1 | length 694.9
  Top Layer w12: LED120.1@6886.35,5253.33 7485.59,5253.33 7529.15,5296.94 LED119.3@7563.19,5296.94
$1N5700: LED120.3 LED121.1 | length 694.9
  Top Layer w12: LED121.1@6136.35,5253.33 6735.59,5253.33 6779.15,5296.94 LED120.3@6813.19,5296.94
$1N5702: LED122.3 LED123.1 | length 1010.1
  Top Layer w12: LED123.1@4321.35,5253.33 4920.59,5253.33 4964.15,5296.94 5312.93,5296.94 LED122.3@5313.24,5296.64
$1N5704: LED123.3 LED124.1 | length 694.9
  Top Layer w12: LED124.1@3571.35,5253.33 4170.59,5253.33 4214.15,5296.94 LED123.3@4248.19,5296.94
$1N5706: LED121.3 LED122.1 | length 694.9
  Top Layer w12: LED122.1@5386.35,5253.33 5985.59,5253.33 6029.15,5296.94 LED121.3@6063.19,5296.94
$1N5840: LED125.3 LED126.1 | length 694.9
  Top Layer w12: LED126.1@6886.35,4503.33 7485.59,4503.33 7529.15,4546.94 LED125.3@7563.19,4546.94
$1N5842: LED126.3 LED127.1 | length 694.9
  Top Layer w12: LED127.1@6136.35,4503.33 6735.59,4503.33 6779.15,4546.94 LED126.3@6813.19,4546.94
$1N5844: LED128.3 LED129.1 | length 1010.1
  Top Layer w12: LED129.1@4321.35,4503.33 4920.59,4503.33 4964.15,4546.94 5312.93,4546.94 LED128.3@5313.24,4546.64
$1N5846: LED129.3 LED130.1 | length 694.9
  Top Layer w12: LED130.1@3571.35,4503.33 4170.59,4503.33 4214.15,4546.94 LED129.3@4248.19,4546.94
$1N5848: LED127.3 LED128.1 | length 694.9
  Top Layer w12: LED128.1@5386.35,4503.33 5985.59,4503.33 6029.15,4546.94 LED127.3@6063.19,4546.94
$1N6551: LED143.1 LED144.3 | length 694.9
  Top Layer w12: LED143.1@8701.35,6753.33 9300.59,6753.33 9344.15,6796.94 LED144.3@9378.19,6796.94
$1N6575: LED144.1 LED145.3 | length 694.9
  Top Layer w12: LED144.1@9451.35,6753.33 10050.59,6753.33 10094.15,6796.94 LED145.3@10128.19,6796.94
$1N6687: LED146.1 LED147.3 | length 694.9
  Top Layer w12: LED146.1@8701.35,4878.33 9300.59,4878.33 9344.15,4921.94 LED147.3@9378.19,4921.94
$1N6689: LED147.1 LED148.3 | length 694.9
  Top Layer w12: LED147.1@9451.35,4878.33 10050.59,4878.33 10094.15,4921.94 LED148.3@10128.19,4921.94
$1N7005: LED1.1 LED82.3 | length 9644.8
  Top Layer w12: LED82.3@3498.24,11176.64 3500,11178.4 3500,11220.8 3525,11245.8 12225,11245.8 12250,11270.8 12250,11845.8 12212.47,11883.33 LED1.1@12011.35,11883.33
$1N7014: LED76.3 LED78.1 | length 1015.1
  Top Layer w12: LED78.1@5066.35,11133.33 5233.33,11133.33 5250,11150 5687.24,11150 5714.15,11176.94 6062.93,11176.94 LED76.3@6063.24,11176.64
$1N7019: LED70.3 LED72.1 | length 1010.1
  Top Layer w12: LED72.1@7636.35,11133.33 8235.59,11133.33 8279.15,11176.94 8627.93,11176.94 LED70.3@8628.24,11176.64
$1N7024: LED64.1 LED88.3 | length 8874.8
  Top Layer w12: LED88.3@3498.24,10111.64 3500,10113.4 3500,10145.8 3525,10170.8 11150,10170.8 11175,10195.8 11175,11095.8 11137.47,11133.33 LED64.1@10946.35,11133.33
$1N7034: LED85.3 LED86.1 | length 1010.1
  Top Layer w12: LED86.1@5071.35,10068.33 5670.59,10068.33 5714.15,10111.94 6062.93,10111.94 LED85.3@6063.24,10111.64
$1N7039: LED83.1 LED139.3 | length 1010.1
  Top Layer w12: LED83.1@7636.35,10068.33 8235.59,10068.33 8279.15,10111.94 8627.93,10111.94 LED139.3@8628.24,10111.64
$1N7044: LED135.3 LED139.1 | length 1070.1
  Top Layer w12: LED139.1@8701.35,10068.33 9300.59,10068.33 9344.15,10111.94 9752.93,10111.94 LED135.3@9753.24,10111.64
$1N7049: LED131.3 LED135.1 | length 1070.1
  Top Layer w12: LED135.1@9826.35,10068.33 10425.59,10068.33 10469.15,10111.94 10877.93,10111.94 LED131.3@10878.24,10111.64
$1N7054: LED94.3 LED131.1 | length 8568.6
  Top Layer w12: LED94.3@3498.24,9361.64 3500,9363.4 3500,9395.8 3525,9420.8 11150,9420.8 11175,9445.8 11175,10045.8 11152.47,10068.33 LED131.1@10946.35,10068.33
$1N7064: LED91.3 LED92.1 | length 1010.1
  Top Layer w12: LED92.1@5071.35,9318.33 5670.59,9318.33 5714.15,9361.94 6062.93,9361.94 LED91.3@6063.24,9361.64
$1N7074: LED132.3 LED136.1 | length 1070.1
  Top Layer w12: LED136.1@9826.35,9318.33 10425.59,9318.33 10469.15,9361.94 10877.93,9361.94 LED132.3@10878.24,9361.64
$1N7093: LED97.3 LED98.1 | length 1010.1
  Top Layer w12: LED98.1@5071.35,8568.33 5670.59,8568.33 5714.15,8611.94 6062.93,8611.94 LED97.3@6063.24,8611.64
$1N7122: LED133.3 LED137.1 | length 1070.1
  Top Layer w12: LED137.1@9826.35,8568.33 10425.59,8568.33 10469.15,8611.94 10877.93,8611.94 LED133.3@10878.24,8611.64
$1N7126: LED106.3 LED133.1 | length 8568.6
  Top Layer w12: LED106.3@3498.24,7861.64 3500,7863.4 3500,7895.8 3525,7920.8 11150,7920.8 11175,7945.8 11175,8545.8 11152.47,8568.33 LED133.1@10946.35,8568.33
$1N7136: LED103.3 LED104.1 | length 1010.1
  Top Layer w12: LED104.1@5071.35,7818.33 5670.59,7818.33 5714.15,7861.94 6062.93,7861.94 LED103.3@6063.24,7861.64
$1N7141: LED101.1 LED142.3 | length 1010.1
  Top Layer w12: LED101.1@7636.35,7818.33 8235.59,7818.33 8279.15,7861.94 8627.93,7861.94 LED142.3@8628.24,7861.64
$1N7146: LED138.3 LED142.1 | length 1070.1
  Top Layer w12: LED142.1@8701.35,7818.33 9300.59,7818.33 9344.15,7861.94 9752.93,7861.94 LED138.3@9753.24,7861.64
$1N7151: LED134.3 LED138.1 | length 1070.1
  Top Layer w12: LED138.1@9826.35,7818.33 10425.59,7818.33 10469.15,7861.94 10877.93,7861.94 LED134.3@10878.24,7861.64
$1N7156: LED112.3 LED134.1 | length 8883.6
  Top Layer w12: LED112.3@3498.24,6796.64 3500,6798.4 3500,6820.8 3525,6845.8 11150,6845.8 11175,6870.8 11175,7795.8 11152.47,7818.33 LED134.1@10946.35,7818.33
$1N7163: LED107.1 LED143.3 | length 1010.1
  Top Layer w12: LED107.1@7636.35,6753.33 8235.59,6753.33 8279.15,6796.94 8627.93,6796.94 LED143.3@8628.24,6796.64
$1N7168: LED118.3 LED145.1 | length 7813.8
  Top Layer w12: LED118.3@3498.24,6046.64 3498.24,6070.8 3524.12,6096.68 10400.88,6096.68 10425,6120.8 10425,6720.8 10392.47,6753.33 LED145.1@10196.35,6753.33
$1N7178: LED2.1 LED124.3 | length 7218.1
  Top Layer w12: LED124.3@3498.24,5296.64 3500,5298.4 3500,5320.8 3525,5345.8 7910,5345.8 8285,4970.8 9650,4970.8 9675,4995.8 9675,5595.8 9642.47,5628.33 LED2.1@9446.35,5628.33
$1N7185: LED119.1 LED146.3 | length 1129.3
  Top Layer w12: LED119.1@7636.35,5253.33 7932.47,5253.33 8264.16,4921.64 LED146.3@8628.24,4921.64
$1N7211: LED3.3 LED125.1 | length 1879.3
  Top Layer w12: LED125.1@7636.35,4503.33 7932.47,4503.33 8264.16,4171.64 LED3.3@9378.24,4171.64
$1N7217: LED3.1 LED153.3 | length 2290.2
  Top Layer w12: LED3.1@9451.35,4128.33 10851.69,4128.33 11270,4546.64 LED153.3@11568.24,4546.64
$1N7239: LED4.1 LED5.3 | length 1820.1
  Top Layer w12: LED4.1@5386.35,3753.33 5985.59,3753.33 6029.15,3796.94 7187.93,3796.94 LED5.3@7188.24,3796.64
$1N7386: SW1.2 SW153.2 SW154.2 SW155.2 U1.15 | length 9169.1
  Top Layer w12: v1(11325,11625) U1.15@11325,11707.7
  Bottom Layer w12: v1(11325,11625) 11325,11600 ; SW155.2@11502.29,3374.97 SW153.2@11502.29,4124.97 SW154.2@11502.29,4874.97 11277.29,4874.97 11277.29,11552.29 11325,11600 ; SW1.2@11877.29,11504.97 11782.26,11600 11325,11600
$1N7677: D107.2 D108.2 D109.2 D110.2 D111.2 D112.2 D143.2 D144.2 D145.2 R7.1 U3.12 | length 12413.9
  Top Layer w12: D112.2@3682.29,6168.81 3899.31,6168.81 ; v1(3900,6200) 3900,6169.5 3899.31,6168.81 ; v1(5525,11375) 5525,11650 5550,11675 U3.12@5550,11782.7 R7.1@5550,11857.96 ; v1(5650,6225) 5650,6171.68 5647.14,6168.81 ; D145.2@10312.29,6168.81 D144.2@9562.29,6168.81 D143.2@8812.29,6168.81 D107.2@7747.29,6168.81 D108.2@6997.29,6168.81 D109.2@6247.29,6168.81 5647.14,6168.81 ; 3899.31,6168.81 D111.2@4432.29,6168.81 D110.2@5497.29,6168.81 5647.14,6168.81
  Bottom Layer w12: v1(5525,11375) 5525,11325 5650,11200 v1(5650,6225)
$1N7690: D2.2 D113.2 D114.2 D115.2 D116.2 D117.2 D118.2 R8.1 U3.11 | length 12595.3
  Top Layer w12: D118.2@3682.29,5418.81 3854.48,5418.81 ; v1(3850,5475) 3850,5423.29 3854.48,5418.81 ; v1(5575,11375) 5575,11650 5600,11675 U3.11@5600,11782.7 R8.1@5600,11857.96 ; v1(5700,5475) 5700,5420.43 5701.62,5418.81 ; D2.2@9562.29,5043.81 8285,5043.81 7910,5418.81 D113.2@7747.29,5418.81 D114.2@6997.29,5418.81 D115.2@6247.29,5418.81 5701.62,5418.81 ; 3854.48,5418.81 D117.2@4432.29,5418.81 D116.2@5497.29,5418.81 5701.62,5418.81
  Bottom Layer w12: v1(5575,11375) 5700,11250 v1(5700,5475)
$1N7722: D4.2 D5.2 D155.2 P2.10 R11.1 U4.11 | length 16840.4
  Top Layer w12: P2.10@3625,3225 3681.19,3168.81 4643.81,3168.81 4700,3225 ; v1(4700,3350) 4700,3225 ; v1(4700,11300) 4700,11675 4725,11700 U4.11@4725,11782.7 R11.1@4725,11857.96 ; D155.2@11752.29,3168.81 D5.2@7372.29,3168.81 D4.2@5497.29,3168.81 4756.19,3168.81 4700,3225
  Bottom Layer w12: v1(4700,3350) v1(4700,11300)
$1N7845: LED100.3 LED132.1 | length 8935.3
  Top Layer w12: LED100.3@3498.24,8611.64 3498.24,8636.64 3500,8638.4 3500,8670.8 3525,8695.8 7900,8695.8 8300,8295.8 9025,8295.8 9425,8695.8 11150,8695.8 11175,8720.8 11175,9320.8 11152.47,9343.33 10978.6,9343.33 10967.68,9332.4 10960.42,9332.4 LED132.1@10946.35,9318.33
$1N7861: D89.2 D90.2 D91.2 D92.2 D93.2 D94.2 D132.2 D136.2 D141.2 R4.1 U3.3 | length 11015.7
  Top Layer w12: D94.2@3682.29,8733.81 3973.8,8733.81 ; v1(3975,8750) 3975,8735.01 3973.8,8733.81 ; v1(5450,11350) U3.3@5450,11567.3 5450,11650 5475,11675 R4.1@5475,11957.96 ; v1(5575,8775) 5575,8735.01 5576.2,8733.81 ; D132.2@11062.29,8733.81 D136.2@9937.29,8733.81 9388.01,8733.81 9000,8345.8 8825.3,8345.8 D141.2@8812.29,8358.81 8799.28,8345.8 8325,8345.8 7936.99,8733.81 D89.2@7747.29,8733.81 D90.2@6997.29,8733.81 D91.2@6247.29,8733.81 5576.2,8733.81 ; 3973.8,8733.81 D93.2@4432.29,8733.81 D92.2@5182.29,8733.81 5576.2,8733.81
  Bottom Layer w12: v1(5450,11350) 5450,11250 5575,11125 v1(5575,8775)
$1N7870: LED89.1 LED141.3 | length 1129.3
  Top Layer w12: LED89.1@7636.35,9318.33 7946.54,9318.33 8278.24,8986.64 LED141.3@8628.24,8986.64
$1N7875: LED136.3 LED141.1 | length 1230.2
  Top Layer w12: LED141.1@8696.35,8943.33 9035,8943.33 9453.31,9361.64 LED136.3@9753.24,9361.64
$1N7950: LED95.1 LED137.3 | length 2402
  Top Layer w12: LED95.1@7636.35,8568.33 7952.47,8568.33 8275,8245.8 9050,8245.8 9415.84,8611.64 LED137.3@9753.24,8611.64
$1N8062: LED130.3 LED154.1 | length 9579.2
  Top Layer w12: LED130.3@3498.24,4546.64 3496.46,4548.41 3496.46,4569.62 3521.46,4594.62 7911.46,4594.62 8286.46,4219.62 10873.82,4219.62 11248.82,4594.62 11846.46,4594.62 11871.46,4619.62 11871.46,5219.62 11838.94,5252.15 11637.52,5252.15 LED154.1@11636.35,5253.33
$1N8084: LED4.3 LED153.1 | length 7771.1
  Top Layer w12: LED4.3@5313.24,3796.64 5313.24,3820.8 5337.06,3844.63 ; 5338.24,3845.8 5337.06,3844.63 ; LED153.1@11636.35,4503.33 11842.47,4503.33 11875,4470.8 11875,3870.8 11850,3845.8 11472.63,3845.8 11471.46,3844.63 11263.83,3844.63 10888.83,3469.63 8291.17,3469.63 7916.17,3844.63 5337.06,3844.63
$1N8092: LED2.3 LED113.1 | length 1880
  Top Layer w12: LED113.1@7636.35,6003.33 7932.47,6003.33 8265,5670.8 9377.4,5670.8 LED2.3@9378.24,5671.64
$1N8140: LED148.1 LED154.3 | length 1540.2
  Top Layer w12: LED148.1@10201.35,4878.33 10857.53,4878.33 11275.84,5296.64 LED154.3@11568.24,5296.64
$1N8347: LED5.1 LED155.3 | length 4604.6
  Top Layer w12: LED5.1@7256.35,3753.33 7932.47,3753.33 8264.16,3421.64 10894.99,3421.64 11270,3796.64 LED155.3@11568.24,3796.64
$1N8764: LED149.1 LED150.3 | length 1445.1
  Top Layer w12: LED149.1@12161.26,10507.4 12161.26,9908.15 12204.87,9864.59 12204.87,9830.55 12204.57,9830.25 LED150.3@12204.57,9080.51
$1N8766: LED150.1 LED151.3 | length 1445.1
  Top Layer w12: LED150.1@12161.26,9007.4 12161.26,8408.15 12204.87,8364.59 12204.87,7580.81 LED151.3@12204.57,7580.51
$1N8768: LED151.1 LED152.3 | length 1503.2
  Top Layer w12: LED151.1@12161.26,7507.4 12161.26,7313.66 12275,7200.02 12275,6150.94 LED152.3@12204.57,6080.51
